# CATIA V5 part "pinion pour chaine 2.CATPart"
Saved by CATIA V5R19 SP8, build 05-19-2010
Part number: pinion pour chaine 2
Bounding box of the stored display mesh (mm): x -31 to 31, y -22 to 0, z -31 to 31
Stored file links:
  G:\EU_thinkMotion\CFAO_2010\MMS_groupe1\MMS_groupe1\A reprendre\OK\rdeneffle\pinion pour chaine 2.CATPart
  G:\EU_thinkMotion\CFAO_2010\MMS_groupe1\MMS_groupe1\A reprendre\OK\rdeneffle\pinion pour chaine.CATPart
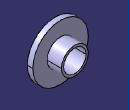
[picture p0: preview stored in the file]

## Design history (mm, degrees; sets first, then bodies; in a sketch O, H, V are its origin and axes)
Body1 (main body)
Body2
  Sketch1 on zx-plane, origin (0, 0, 0), H (-1, 0, 0), V (0, 0, 1)
    circle A1 centre (0, 0) radius 31
    radius A1 = 31
  Pad1: profile Sketch1, direction (0, -1, 0), length 22
  Sketch2 on start face of Pad1, origin (0, 0, 0), H (-1, 0, 0), V (0, 0, 1)
    circle A1 centre (0, 0) radius 15
    circle A2 centre (0, 0) radius 31
    point P1 (0, -31)
    reference projected circle E1 centre (0, 0) radius 31 from edge [face of Pad1 from Sketch1.A1 | start face of Pad1]
    radius A1 = 15
    coincidence: A2 P1, P1 V, A2 E1
  Pocket1: profile Sketch2, direction (0, -1, 0), length 16
  Sketch3 on start face of Pad1, origin (0, 0, 0), H (-1, 0, 0), V (0, 0, 1)
    circle A1 centre (0, 0) radius 12.5
    radius A1 = 12.5
  Pocket2: profile Sketch3, direction (0, -1, 0), length 22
